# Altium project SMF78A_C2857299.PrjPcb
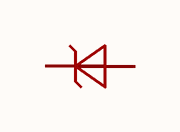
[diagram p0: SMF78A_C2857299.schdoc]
1 sheet, 1 parts. Net scope: global (net labels, ports and power ports of the same name join across sheets).

## Sheet SMF78A_C2857299.schdoc
size 127 x 101 mm

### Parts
D?  smf78a_c2857299  [SOD-123FL_L2.7-W1.8-LS3.7-RD]  (value not drawn)

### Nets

Not connected (* = marked no-connect by the designer): D? 1 2

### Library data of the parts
D? = smf78a_c2857299: 极性:单向;反向截止电压(Vrwm):78V;钳位电压:126V;峰值脉冲电流(Ipp):1.6A;峰值脉冲功率(Ppp):200W@10/1000us;击穿电压(VBR):86.7V;; Manufacturer: JSMSEMI(杰盛微); ManufacturerPart: SMF78A; AddInBom: yes; ModelId: 86f9151e155e4fe2af0c4f2e0a80302e; ModelName: SOD-123FL_L2.8-W1.8-H1.1-LS3.6; ModelTransform: 141.732,70.866,0,180,0,0,0,0,0; Polarity: 单向; Reverse Stand-Off Voltage (Vrwm): 78V; Clamping Voltage: 126V; Peak Pulse Current (Ipp): 1.6A; Voltage - Breakdown: 86.7V; Reverse Leakage Current (Ir): 1uA; Number of Channels: 单路; Type: TVS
